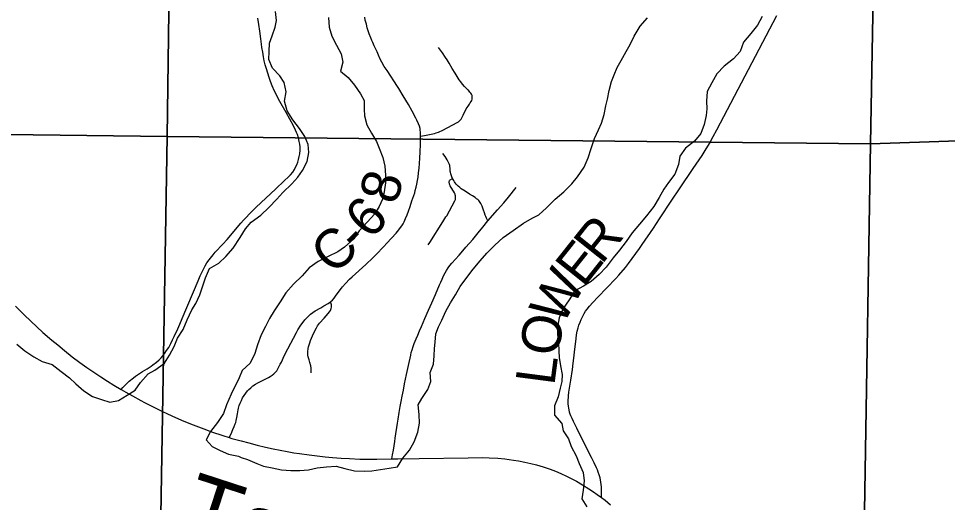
# Model space of a CAD drawing. Extents: x 0 to 34, y 0 to 22.
# Drawn here: x 22.024 to 23.369, y 16.109 to 16.809 of the extents above; entities that cross this region are included whole.
import ezdxf

# ---------------------------------------------------------------- set-up
doc = ezdxf.new("R2010")
doc.units = 0
for name, color, linetype in [('GM_X_Corporation', 7, 'Continuous'), ('GM_X_County_Road', 7, 'Continuous'), ('GM_X_County_Road_Text', 7, 'Continuous'), ('GM_X_Major_Lake', 7, 'Continuous'), ('GM_X_Major_Lake_Text', 7, 'Continuous'), ('GM_X_State_Route', 7, 'Continuous'), ('GM_X_Township_Road', 7, 'Continuous'), ('GM_X_US_Route', 7, 'Continuous')]:
    doc.layers.add(name, color=color, linetype=linetype)

msp = doc.modelspace()

# ---------------------------------------------------------------- linework, layer by layer
at = {"layer": 'GM_X_Corporation'}
for points in [[(22.2529, 17.6514), (22.2392, 16.6385), (21.2309, 16.6512), (21.2422, 17.6682)], [(22.2529, 17.6514), (23.2763, 17.6399), (23.2579, 16.628), (22.2392, 16.6385)], [(23.2763, 17.6399), (24.2773, 17.6357), (24.2765, 17.4936), (24.2698, 16.6327), (23.7676, 16.6453), (23.2579, 16.628)], [(21.2309, 16.6512), (22.2392, 16.6385), (22.2224, 15.6282), (21.2159, 15.6439)], [(23.2579, 16.628), (23.7676, 16.6453), (24.2698, 16.6327), (24.2658, 16.4792), (24.2407, 15.6067), (23.2418, 15.623)], [(22.2392, 16.6385), (23.2579, 16.628), (23.2418, 15.623), (22.2224, 15.6282)]]:
    msp.add_lwpolyline(points, close=True, dxfattribs=at)
at = {"layer": 'GM_X_County_Road'}
for points in [[(22.3293, 16.203), (22.3319, 16.2086), (22.3346, 16.2146), (22.3364, 16.2189), (22.3379, 16.223), (22.3386, 16.2249), (22.3393, 16.2278), (22.3401, 16.2323), (22.3412, 16.2376), (22.3422, 16.2432), (22.3427, 16.2456), (22.3432, 16.2477), (22.3437, 16.2494), (22.3451, 16.2529), (22.3468, 16.2566), (22.3487, 16.2604), (22.3508, 16.2638), (22.3531, 16.2672), (22.3557, 16.2705), (22.3575, 16.2725), (22.3604, 16.2751), (22.3636, 16.2777), (22.3671, 16.2801), (22.3708, 16.2824), (22.3753, 16.2847), (22.3831, 16.2884), (22.3859, 16.29), (22.3883, 16.2913), (22.3914, 16.2934), (22.3938, 16.2954), (22.3959, 16.2973), (22.398, 16.2998), (22.3996, 16.3024), (22.4032, 16.3092), (22.4048, 16.3123), (22.409, 16.3213), (22.4141, 16.3314), (22.4265, 16.355), (22.4287, 16.3589), (22.433, 16.3657), (22.4347, 16.3683), (22.4389, 16.3736), (22.4406, 16.3754), (22.444, 16.3787), (22.4471, 16.3815), (22.4503, 16.3839), (22.4537, 16.3862), (22.462, 16.3908), (22.4665, 16.3935), (22.4726, 16.3971), (22.4744, 16.3983), (22.4757, 16.3993), (22.4771, 16.4005), (22.4786, 16.4019), (22.4811, 16.4047), (22.4843, 16.4089), (22.4919, 16.4191), (22.4935, 16.4212), (22.4977, 16.426), (22.5036, 16.432), (22.5075, 16.4355), (22.527, 16.4536), (22.5371, 16.4633), (22.5419, 16.468), (22.5534, 16.4797), (22.5577, 16.4843), (22.5709, 16.4988), (22.5749, 16.5034), (22.5775, 16.5068), (22.5793, 16.5093), (22.5813, 16.5124), (22.5828, 16.5152), (22.5847, 16.5199), (22.5868, 16.5253), (22.5887, 16.5304), (22.5912, 16.5374), (22.5939, 16.5454), (22.5979, 16.5574), (22.5987, 16.5603), (22.6002, 16.5652), (22.6012, 16.5697), (22.602, 16.5749), (22.6028, 16.5798), (22.6036, 16.5863), (22.6045, 16.5929), (22.6049, 16.5995), (22.6055, 16.6073), (22.6058, 16.6163), (22.6062, 16.627), (22.6062, 16.6393), (22.6061, 16.645), (22.6059, 16.648), (22.6056, 16.6502), (22.6046, 16.6535), (22.6032, 16.6569), (22.6008, 16.6621), (22.5996, 16.6652), (22.5944, 16.6752), (22.5888, 16.6849), (22.5813, 16.6976), (22.575, 16.708), (22.5731, 16.711), (22.5578, 16.7343), (22.5537, 16.74), (22.5503, 16.746), (22.5479, 16.7506), (22.5454, 16.7563), (22.5433, 16.7613), (22.5411, 16.7661), (22.5393, 16.7701), (22.5373, 16.7745), (22.5358, 16.7776), (22.5342, 16.7814), (22.532, 16.7871), (22.5306, 16.7914), (22.5292, 16.7961), (22.5279, 16.801), (22.5263, 16.8072), (22.5255, 16.8112)], [(22.8682, 16.1164), (22.8686, 16.1217), (22.8685, 16.1272), (22.8682, 16.1319), (22.8674, 16.1387), (22.8663, 16.145), (22.8651, 16.1489), (22.8636, 16.1531), (22.8624, 16.1565), (22.8611, 16.1592), (22.8578, 16.1663), (22.8538, 16.1743), (22.845, 16.1921), (22.8329, 16.2164), (22.8278, 16.2262), (22.8257, 16.2308), (22.8242, 16.2344), (22.8232, 16.2369), (22.8222, 16.24), (22.8215, 16.2431), (22.821, 16.2456), (22.8207, 16.2484), (22.8203, 16.2519), (22.8202, 16.2554), (22.8204, 16.2632), (22.8213, 16.2688), (22.8226, 16.2773), (22.8242, 16.2863), (22.8265, 16.3016), (22.8276, 16.3107), (22.8283, 16.3178), (22.8294, 16.3268), (22.8316, 16.3462), (22.8324, 16.3518), (22.8334, 16.3571), (22.8345, 16.3618), (22.8357, 16.3656), (22.8374, 16.37), (22.839, 16.3738), (22.8413, 16.3787), (22.8433, 16.3825), (22.8453, 16.3857), (22.8477, 16.389), (22.8512, 16.3931), (22.8558, 16.3984), (22.8631, 16.4062), (22.8894, 16.4334), (22.8936, 16.438), (22.9031, 16.4493), (22.9076, 16.455), (22.9235, 16.4766), (22.9275, 16.4822), (22.9437, 16.5061), (22.9525, 16.5194), (22.9702, 16.5466), (22.9812, 16.5628), (23.0013, 16.5924), (23.014, 16.611), (23.0187, 16.6183), (23.0247, 16.6284), (23.0302, 16.6387), (23.0355, 16.6484), (23.1226, 16.814)]]:
    msp.add_lwpolyline(points, dxfattribs=at)
at = {"layer": 'GM_X_Major_Lake'}
for points in [[(22.3526, 16.5049), (22.3612, 16.5148), (22.3748, 16.5248), (22.3864, 16.536), (22.3984, 16.5478), (22.407, 16.5578), (22.4198, 16.5701), (22.4284, 16.58), (22.4352, 16.5896), (22.4422, 16.6025), (22.4444, 16.6154), (22.4435, 16.6272), (22.4389, 16.6385), (22.4308, 16.6502), (22.4212, 16.663), (22.4131, 16.6758), (22.4092, 16.6898), (22.4117, 16.7031), (22.4089, 16.7167), (22.4024, 16.7265), (22.3921, 16.7374), (22.3866, 16.7503), (22.3869, 16.7616), (22.3875, 16.7738), (22.3912, 16.7841), (22.396, 16.797), (22.3978, 16.8065), (22.3962, 16.8194)], [(22.3428, 16.1759), (22.3463, 16.174), (22.3558, 16.1711), (22.3691, 16.1655), (22.379, 16.1618), (22.3915, 16.1593), (22.4048, 16.1564), (22.4184, 16.1554), (22.4317, 16.1555), (22.4442, 16.1564), (22.4566, 16.1592), (22.4703, 16.1609), (22.4843, 16.1618), (22.4968, 16.1581), (22.5109, 16.1548), (22.5249, 16.1542), (22.5359, 16.1547), (22.5608, 16.1587), (22.5729, 16.1608), (22.5808, 16.173), (22.5901, 16.1848), (22.5972, 16.1971), (22.6024, 16.2108), (22.6046, 16.2237), (22.6041, 16.2366), (22.6028, 16.2502), (22.6084, 16.2598), (22.617, 16.2724), (22.621, 16.2842), (22.6202, 16.2971), (22.625, 16.3093), (22.626, 16.3214), (22.6267, 16.3317), (22.6273, 16.3411), (22.6287, 16.3533), (22.6321, 16.3632), (22.6373, 16.3727), (22.6428, 16.3857), (22.6495, 16.3979), (22.657, 16.4094), (22.6637, 16.4216), (22.6734, 16.4346), (22.6824, 16.4468), (22.6925, 16.4586), (22.7023, 16.4697), (22.7139, 16.4812), (22.7259, 16.4924), (22.7406, 16.5028), (22.7553, 16.5135), (22.7681, 16.5205), (22.7779, 16.5255), (22.7888, 16.5355), (22.8012, 16.5481), (22.8139, 16.5585), (22.8256, 16.5704), (22.8338, 16.5803), (22.8435, 16.5941), (22.8491, 16.6078), (22.8535, 16.6211), (22.8583, 16.6356), (22.8639, 16.6485), (22.8683, 16.658), (22.8724, 16.6706), (22.8745, 16.6831), (22.8771, 16.6926), (22.8796, 16.7052), (22.8829, 16.7185), (22.8866, 16.728), (22.891, 16.7383), (22.897, 16.7486), (22.9041, 16.7619), (22.91, 16.7719), (22.9156, 16.7837), (22.9242, 16.7982), (22.935, 16.8104)], [(22.4728, 16.8107), (22.4741, 16.797), (22.478, 16.7838), (22.4846, 16.7706), (22.4915, 16.7585), (22.4939, 16.7464), (22.4902, 16.7331), (22.5017, 16.7241), (22.5105, 16.7128), (22.5193, 16.7004), (22.5247, 16.6906), (22.5249, 16.6781), (22.525, 16.6686), (22.5285, 16.6554), (22.5354, 16.6437), (22.5424, 16.6316), (22.5466, 16.6218), (22.5517, 16.6082), (22.5544, 16.5957), (22.5557, 16.5828), (22.5558, 16.5718), (22.5537, 16.5585), (22.5511, 16.5479), (22.5463, 16.5372), (22.5399, 16.5269), (22.5291, 16.5146), (22.5174, 16.5024), (22.5096, 16.4906), (22.4961, 16.4787), (22.4863, 16.4717), (22.4727, 16.4651), (22.458, 16.4578), (22.4448, 16.4486)], [(23.101, 16.8125), (23.0946, 16.7999), (23.0845, 16.7877), (23.074, 16.7754), (23.0692, 16.7617), (23.0595, 16.751), (23.046, 16.7406), (23.0355, 16.7295), (23.028, 16.7165), (23.0213, 16.704), (23.0207, 16.6899), (23.0208, 16.6786), (23.0201, 16.6691), (23.0172, 16.6558), (23.0124, 16.6432), (23.0031, 16.6317), (22.9903, 16.6217), (22.9817, 16.6103), (22.9799, 16.5981), (22.9747, 16.5844), (22.9657, 16.5722), (22.9586, 16.5626), (22.9519, 16.5504), (22.9441, 16.5374), (22.9336, 16.5241), (22.9235, 16.5118), (22.913, 16.4992), (22.904, 16.4866), (22.8943, 16.4743), (22.8853, 16.4633), (22.8752, 16.4495), (22.8651, 16.4388), (22.8534, 16.4288), (22.8425, 16.4222), (22.8297, 16.4153), (22.8215, 16.4023), (22.8129, 16.3897), (22.8073, 16.3764), (22.8048, 16.3627), (22.8049, 16.3528), (22.8062, 16.3407), (22.8067, 16.3282), (22.8071, 16.3187), (22.8091, 16.3066), (22.8115, 16.2941), (22.8109, 16.2842), (22.8087, 16.2747), (22.8058, 16.2618), (22.8002, 16.2488), (22.8003, 16.2355), (22.8111, 16.2235), (22.813, 16.2129), (22.8207, 16.2012), (22.8246, 16.1902), (22.8316, 16.1767), (22.8362, 16.1653), (22.842, 16.1525), (22.8433, 16.1403), (22.8419, 16.1271), (22.8401, 16.1145), (22.847, 16.1028)], [(22.0215, 16.3384), (22.0334, 16.3287), (22.046, 16.3197), (22.0585, 16.313), (22.073, 16.3086), (22.0859, 16.2985), (22.0978, 16.2895), (22.1073, 16.2809), (22.1188, 16.2707), (22.1314, 16.2625), (22.1443, 16.2581), (22.1564, 16.2544), (22.1689, 16.2565), (22.1814, 16.2642), (22.193, 16.2715), (22.2009, 16.2826), (22.2118, 16.2952), (22.2216, 16.3006), (22.2355, 16.3106), (22.2426, 16.3221), (22.2493, 16.3347), (22.2545, 16.3469), (22.2623, 16.3595), (22.2682, 16.3732), (22.2749, 16.3877), (22.2809, 16.3972), (22.2868, 16.4098), (22.2949, 16.4341), (22.3009, 16.4479), (22.3141, 16.4552), (22.3242, 16.4648), (22.3351, 16.477), (22.3452, 16.4923), (22.3526, 16.5049)], [(22.4448, 16.4486), (22.4347, 16.4371), (22.4223, 16.4248), (22.4111, 16.4126), (22.4032, 16.3996), (22.3943, 16.3866), (22.3876, 16.3755), (22.382, 16.3637), (22.3757, 16.3519), (22.3701, 16.3374), (22.3661, 16.3248), (22.3594, 16.3107), (22.3481, 16.3), (22.3437, 16.2893), (22.3321, 16.2657), (22.3251, 16.2504), (22.3207, 16.2379), (22.3124, 16.2249), (22.302, 16.2119), (22.2956, 16.1997), (22.3044, 16.1899), (22.3162, 16.1843), (22.3284, 16.1788), (22.3428, 16.1759)]]:
    msp.add_lwpolyline(points, dxfattribs=at)
at = {"layer": 'GM_X_State_Route'}
msp.add_lwpolyline([(22.1729, 16.2724), (22.1753, 16.2753), (22.1825, 16.2829), (22.1845, 16.2847), (22.1907, 16.2897), (22.1937, 16.2918), (22.1993, 16.2957), (22.2036, 16.2985), (22.2103, 16.3025), (22.2164, 16.3065), (22.2188, 16.3082), (22.2241, 16.3123), (22.2279, 16.3156), (22.2307, 16.3185), (22.2333, 16.3214), (22.236, 16.325), (22.2386, 16.3288), (22.2416, 16.3336), (22.2448, 16.3392), (22.2473, 16.3444), (22.2497, 16.3495), (22.2546, 16.3605), (22.2576, 16.3671), (22.261, 16.3753), (22.2842, 16.43), (22.2872, 16.437), (22.29, 16.4429), (22.2923, 16.4476), (22.2943, 16.4514), (22.297, 16.4557), (22.3, 16.4601), (22.3059, 16.4676), (22.3088, 16.4711), (22.3199, 16.483), (22.3262, 16.4898), (22.3459, 16.5133), (22.3499, 16.5178), (22.3626, 16.5308), (22.3684, 16.5365), (22.3962, 16.5625), (22.4094, 16.5748), (22.4145, 16.5796), (22.418, 16.5832), (22.4212, 16.5872), (22.4237, 16.591), (22.4254, 16.5941), (22.4272, 16.5978), (22.4286, 16.6015), (22.4298, 16.6056), (22.4307, 16.6096), (22.4314, 16.6135), (22.4319, 16.6188), (22.4318, 16.6234), (22.4314, 16.6275), (22.4307, 16.6314), (22.4294, 16.6368), (22.4279, 16.6414), (22.4268, 16.6445), (22.4253, 16.648), (22.4222, 16.6539), (22.4116, 16.6732), (22.4024, 16.6891), (22.3991, 16.6957), (22.3966, 16.7007), (22.3948, 16.7044), (22.3915, 16.7122), (22.389, 16.7185), (22.387, 16.7242), (22.385, 16.7304), (22.3831, 16.7367), (22.3815, 16.7424), (22.38, 16.7482), (22.3788, 16.7538), (22.3777, 16.7605), (22.3767, 16.7673), (22.376, 16.7724), (22.3749, 16.78), (22.3734, 16.7911), (22.3721, 16.8008), (22.3706, 16.81)], dxfattribs=at)
at = {"layer": 'GM_X_Township_Road'}
for points in [[(22.6062, 16.6393), (22.6123, 16.6403), (22.6193, 16.6417), (22.6264, 16.6432), (22.6292, 16.644), (22.6323, 16.6451), (22.6386, 16.6479), (22.6451, 16.6512), (22.6533, 16.6554), (22.6594, 16.6589), (22.6612, 16.6601), (22.6625, 16.6611), (22.6642, 16.6627), (22.665, 16.6639), (22.6661, 16.6655), (22.6682, 16.6697), (22.6726, 16.6785), (22.6738, 16.6804), (22.6755, 16.6827), (22.6773, 16.6855), (22.6784, 16.6872), (22.6796, 16.6892), (22.6805, 16.691), (22.6811, 16.6927), (22.6813, 16.6946), (22.6809, 16.698), (22.6802, 16.6997), (22.6791, 16.7013), (22.6779, 16.7029), (22.6757, 16.7055), (22.675, 16.7063), (22.6701, 16.7112), (22.6671, 16.7143), (22.6645, 16.7178), (22.6625, 16.7205), (22.6608, 16.7229), (22.6594, 16.7253), (22.6564, 16.7305), (22.6522, 16.7373), (22.648, 16.7446), (22.645, 16.7494), (22.6427, 16.753), (22.6379, 16.7598), (22.6325, 16.7675)], [(22.7039, 16.5166), (22.7021, 16.5203), (22.7007, 16.5231), (22.6999, 16.5249), (22.6988, 16.5281), (22.6976, 16.5319), (22.6955, 16.538), (22.6948, 16.5398), (22.6937, 16.5417), (22.6928, 16.5433), (22.6917, 16.5448), (22.6906, 16.546), (22.6891, 16.5474), (22.6876, 16.5486), (22.6853, 16.5503), (22.6818, 16.5526), (22.6772, 16.5554), (22.6709, 16.5594), (22.6653, 16.5631), (22.6631, 16.5647), (22.6609, 16.5666), (22.6594, 16.5681), (22.6578, 16.5698), (22.6566, 16.5715), (22.6554, 16.5733), (22.6544, 16.575), (22.6527, 16.5781), (22.6515, 16.5805), (22.651, 16.582), (22.6501, 16.5846), (22.6495, 16.5871), (22.6493, 16.5886), (22.6491, 16.5924), (22.6488, 16.5956), (22.6486, 16.5969), (22.6482, 16.5983), (22.6474, 16.6002), (22.6448, 16.605), (22.642, 16.6095), (22.6388, 16.6142)], [(22.6176, 16.4821), (22.6196, 16.4855), (22.6385, 16.5151), (22.6432, 16.5222), (22.6444, 16.524), (22.6562, 16.5456), (22.6566, 16.5465), (22.657, 16.5476), (22.6571, 16.5487), (22.6572, 16.5498), (22.6571, 16.5519), (22.6569, 16.553), (22.6567, 16.5541), (22.6565, 16.555), (22.656, 16.5561), (22.6553, 16.5572), (22.6494, 16.5673), (22.6489, 16.5682), (22.6476, 16.5724), (22.6475, 16.5731), (22.6477, 16.5737), (22.6482, 16.5748), (22.6489, 16.5755), (22.6493, 16.576), (22.6527, 16.5781)], [(22.7039, 16.5166), (22.718, 16.5326), (22.7268, 16.5429), (22.7338, 16.5511), (22.7447, 16.5647)], [(22.6719, 16.4784), (22.682, 16.4898), (22.6899, 16.4992), (22.6966, 16.5074), (22.7039, 16.5166)], [(22.5646, 16.1721), (22.5657, 16.1781), (22.567, 16.1849), (22.5691, 16.1974), (22.5698, 16.2022), (22.5707, 16.2082), (22.5721, 16.2176), (22.5731, 16.2241), (22.5739, 16.2299), (22.5753, 16.2391), (22.5769, 16.2481), (22.5782, 16.255), (22.5797, 16.2627), (22.5815, 16.2718), (22.5832, 16.2806), (22.586, 16.2944), (22.5889, 16.3075), (22.5921, 16.3224), (22.5929, 16.3259), (22.5942, 16.3302), (22.5958, 16.3349), (22.5973, 16.3392), (22.5999, 16.3457), (22.6022, 16.3513), (22.6047, 16.3573), (22.6076, 16.3637), (22.6125, 16.3751), (22.618, 16.3876), (22.6226, 16.3982), (22.6278, 16.41), (22.6338, 16.4238), (22.6357, 16.4281), (22.6375, 16.4322), (22.6397, 16.4369), (22.6421, 16.4416), (22.644, 16.4449), (22.6463, 16.4484), (22.6488, 16.4518), (22.6517, 16.4555), (22.6621, 16.4671), (22.6699, 16.4761), (22.6719, 16.4784)], [(22.4479, 16.2966), (22.4481, 16.3003), (22.448, 16.3035), (22.4476, 16.3067), (22.4462, 16.3116), (22.445, 16.3156), (22.4436, 16.3199), (22.4432, 16.3221), (22.443, 16.3251), (22.4431, 16.3273), (22.4437, 16.3321), (22.4442, 16.3343), (22.4449, 16.3371), (22.4458, 16.3401), (22.447, 16.3434), (22.4499, 16.3504), (22.4536, 16.3586), (22.4554, 16.362), (22.4573, 16.3649), (22.46, 16.3684), (22.4667, 16.3759), (22.4725, 16.3824), (22.4747, 16.3848), (22.4761, 16.3871), (22.477, 16.3897), (22.4775, 16.3916), (22.4772, 16.3949), (22.4769, 16.3965), (22.4763, 16.3979), (22.4757, 16.3993)]]:
    msp.add_lwpolyline(points, dxfattribs=at)
at = {"layer": 'GM_X_US_Route'}
for points in [[(22.0199, 16.3933), (22.0263, 16.3865), (22.0328, 16.3801), (22.0505, 16.3632), (22.0593, 16.3552), (22.0725, 16.344), (22.0808, 16.337), (22.0905, 16.3291), (22.1019, 16.3199), (22.1131, 16.3115), (22.123, 16.3044), (22.1315, 16.2985), (22.1431, 16.2909), (22.1527, 16.2847), (22.162, 16.279), (22.1729, 16.2724)], [(22.1729, 16.2724), (22.1795, 16.2686), (22.1891, 16.2633), (22.201, 16.2566), (22.2067, 16.2537), (22.2198, 16.2469), (22.2314, 16.2412), (22.2399, 16.2373), (22.2515, 16.2319), (22.2637, 16.2268), (22.277, 16.2214), (22.2924, 16.2156), (22.3036, 16.2115), (22.3198, 16.2061), (22.3293, 16.203), (22.333, 16.2019), (22.3465, 16.1981), (22.3576, 16.1952), (22.3697, 16.192), (22.382, 16.1891), (22.3927, 16.1867), (22.403, 16.1847), (22.4131, 16.1829), (22.423, 16.1811), (22.4311, 16.1799), (22.4451, 16.178), (22.4568, 16.1764), (22.468, 16.1752), (22.479, 16.1742), (22.4914, 16.1733), (22.5036, 16.1726), (22.5182, 16.172), (22.5307, 16.1719), (22.5428, 16.172), (22.5646, 16.1721), (22.5734, 16.1722), (22.6041, 16.1727), (22.6753, 16.1739), (22.6961, 16.1741), (22.7058, 16.1738), (22.7183, 16.1732), (22.7285, 16.1722), (22.7411, 16.1705), (22.7483, 16.1694), (22.7576, 16.1675), (22.7661, 16.1655), (22.7744, 16.1634), (22.7837, 16.1607), (22.794, 16.1571), (22.8017, 16.1542), (22.8094, 16.1509), (22.8179, 16.147), (22.8264, 16.1428), (22.832, 16.1399), (22.841, 16.1347), (22.8501, 16.129), (22.8568, 16.1245), (22.8623, 16.1207), (22.8682, 16.1164), (22.8735, 16.1123), (22.8814, 16.1055)]]:
    msp.add_lwpolyline(points, dxfattribs=at)

# ---------------------------------------------------------------- texts
at = {"layer": 'GM_X_County_Road_Text'}
for s, rotation, p in [('8', 74.4217, (22.5712, 16.5386)), ('6', 48.0795, (22.5344, 16.488)), ('R', 51.3774, (22.8686, 16.4521)), ('C', 43.6878, (22.4809, 16.4366)), ('-', 43.727, (22.5144, 16.4686)), ('E', 51.5022, (22.8422, 16.4188)), ('W', 60.9559, (22.8116, 16.3633)), ('O', 80.9132, (22.8054, 16.3189)), ('L', 82.5608, (22.8, 16.2772))]:
    msp.add_text(s, height=0.0568, rotation=rotation, dxfattribs=at).set_placement(p)
at = {"layer": 'GM_X_Major_Lake_Text'}
msp.add_text('Tappan Lake', height=0.09469, rotation=341.9624, dxfattribs=at).set_placement((22.2549, 16.0633))

doc.saveas('drawing.dxf')
